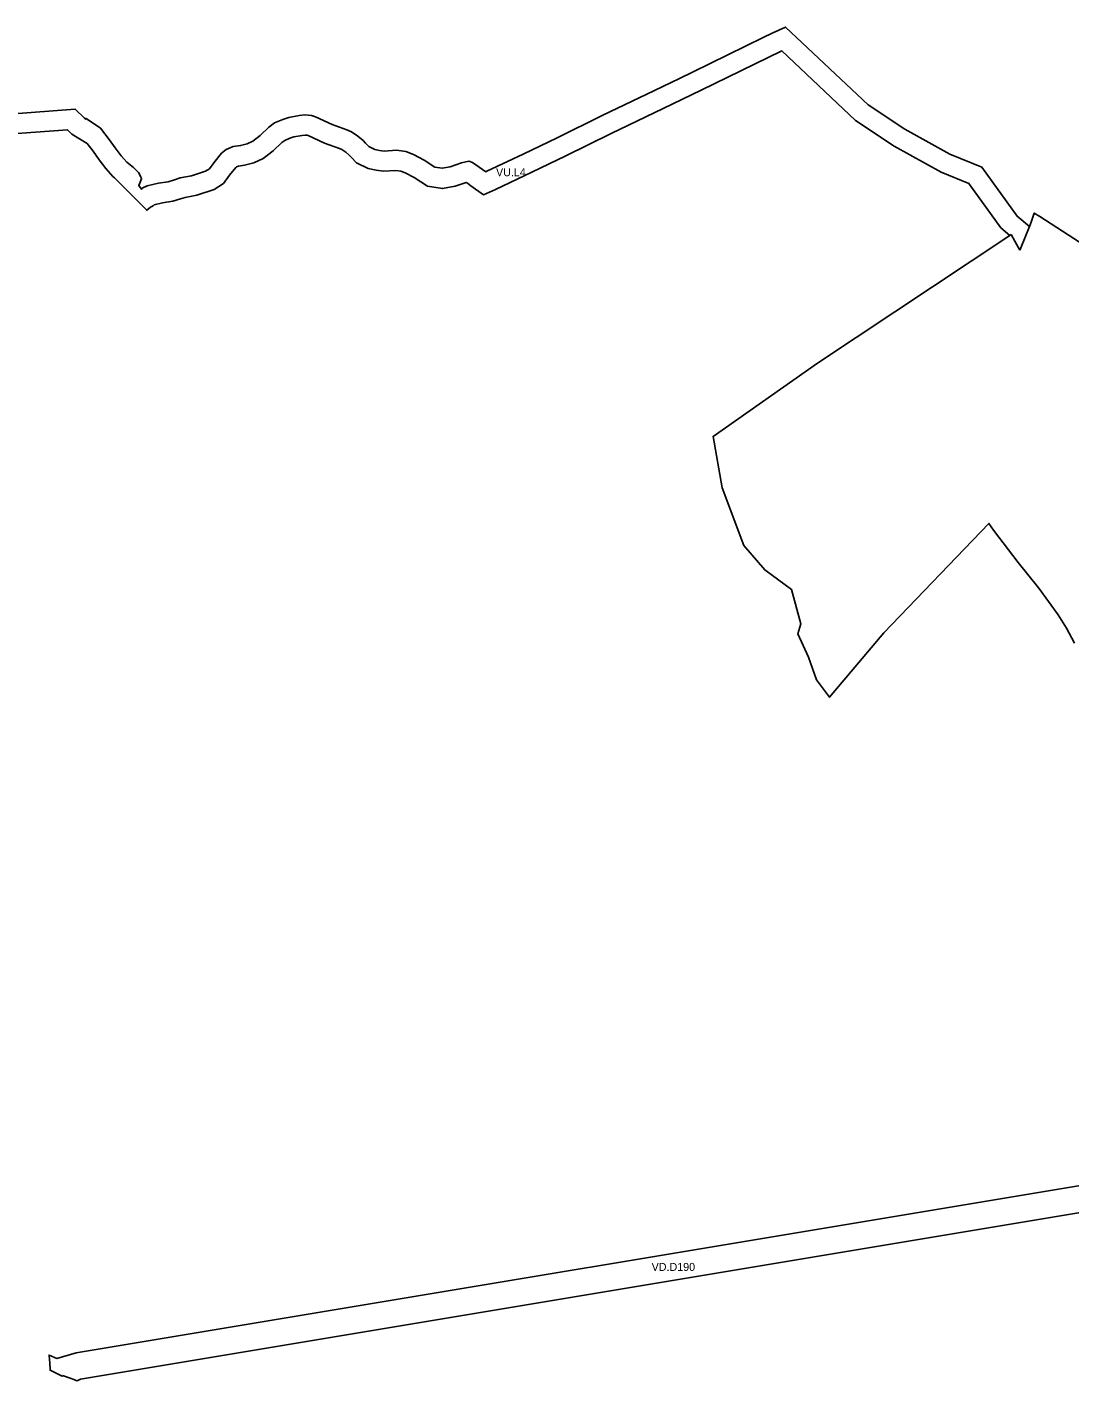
# Model space of a CAD drawing. Extents: x -439083 to -433688, y -1130252 to -1121189.
# Drawn here: x -437411 to -435848, y -1123219 to -1121189 of the extents above; entities that cross this region are included whole.
import ezdxf

# ---------------------------------------------------------------- set-up
doc = ezdxf.new("R2010")
doc.units = 0
for name, color, linetype in [('Vrstva 10', 7, 'Continuous'), ('Vrstva 13', 7, 'Continuous'), ('Vrstva 28', 7, 'Continuous'), ('Vrstva 31', 7, 'Continuous')]:
    doc.layers.add(name, color=color, linetype=linetype)

msp = doc.modelspace()

# ---------------------------------------------------------------- linework, layer by layer
at = {"layer": 'Vrstva 10'}
for p, q in [((-435791.5, -1122919.4), (-437337.2, -1123177)), ((-437330.6, -1123216.5), (-435767.3, -1122955.9)), ((-437357.5, -1123210.9), (-437344.7, -1123215.7))]:
    msp.add_line(p, q, dxfattribs=at)
for points in [[(-437337.2, -1123177), (-437365.9, -1123185.4), (-437377.6, -1123180.5), (-437376.9, -1123187.4), (-437376.9, -1123187.5), (-437376.7, -1123191.5), (-437376, -1123203.1), (-437374.1, -1123203.9), (-437361.9, -1123210), (-437357.9, -1123212), (-437357.5, -1123210.9)], [(-437344.7, -1123215.7), (-437342.2, -1123216.6), (-437335.4, -1123219.1), (-437330.6, -1123216.5)]]:
    msp.add_lwpolyline(points, dxfattribs=at)
at = {"layer": 'Vrstva 28'}
for p, q in [((-435937.7, -1121501.7), (-435935.6, -1121500.3)), ((-435935.6, -1121500.3), (-435937.7, -1121501.7)), ((-435935.6, -1121500.3), (-435932.6, -1121505.9)), ((-435932.6, -1121505.9), (-435935.6, -1121500.3)), ((-435921.2, -1121520.2), (-435908.2, -1121488.6)), ((-435908.2, -1121488.6), (-435921.2, -1121520.2)), ((-435932.6, -1121505.9), (-435922.8, -1121524)), ((-435922.8, -1121524), (-435932.6, -1121505.9)), ((-435922.8, -1121524), (-435921.2, -1121520.2)), ((-435921.2, -1121520.2), (-435922.8, -1121524))]:
    msp.add_line(p, q, dxfattribs=at)
for points in [[(-435908.2, -1121488.6), (-435926.8, -1121473), (-435979.5, -1121399.6), (-436027.7, -1121379.8), (-436095.2, -1121342.5), (-436150.2, -1121305.8), (-436273.7, -1121189.5), (-436293.6, -1121198.8), (-436307.3, -1121205.3), (-436413.3, -1121256.9), (-436432.8, -1121266.4), (-436470.3, -1121284.6), (-436548.5, -1121321.8), (-436616.1, -1121355.7), (-436667.1, -1121379.9), (-436721.3, -1121405.6), (-436722.9, -1121406.4), (-436733.1, -1121399.3), (-436743, -1121392.4), (-436748.4, -1121390.7), (-436759.7, -1121393.2), (-436776.5, -1121399), (-436788.2, -1121401.2), (-436799.2, -1121399.4), (-436815.3, -1121389.1), (-436831.3, -1121380.7), (-436842.9, -1121376.2), (-436856.7, -1121374.2), (-436875.3, -1121375.3), (-436882.6, -1121374.4), (-436889.5, -1121373.1), (-436898.6, -1121368.3), (-436903.3, -1121363.6), (-436906.9, -1121359.6), (-436914.9, -1121353.1), (-436924.1, -1121346.7), (-436931.4, -1121343.5), (-436953.5, -1121335.7), (-436978.2, -1121324.2), (-436984.5, -1121322.1), (-436994.2, -1121321.1), (-437003, -1121322.2), (-437018.2, -1121325), (-437027.3, -1121327.9), (-437039.6, -1121333.1), (-437048.4, -1121339.7), (-437061.1, -1121352.2), (-437072.4, -1121360.7), (-437080.8, -1121364.7), (-437090.6, -1121367.1), (-437101.9, -1121368.7), (-437112, -1121372.9), (-437119.2, -1121378.6), (-437130.8, -1121393.2), (-437137.1, -1121401.8), (-437143, -1121405.5), (-437163.9, -1121412.4), (-437181.2, -1121415.6), (-437189.8, -1121418.4), (-437199, -1121421.4), (-437213.5, -1121423.7), (-437230.6, -1121427.7), (-437237.9, -1121431.2), (-437239.1, -1121432.6), (-437243.2, -1121426.8), (-437239, -1121417.1), (-437240.5, -1121412.8), (-437243.7, -1121407.7), (-437251.2, -1121400.2), (-437261, -1121392), (-437269.4, -1121382.3), (-437278.5, -1121370.5), (-437287.6, -1121357.8), (-437300.4, -1121341.1), (-437322.2, -1121326.5), (-437322.7, -1121327.3), (-437324.6, -1121326.1), (-437338.5, -1121312.5), (-437477.2, -1121322.8)], [(-437466.8, -1121352.1), (-437349.8, -1121343.4), (-437343.3, -1121349.8), (-437320.7, -1121363.9), (-437311.7, -1121375.7), (-437302.6, -1121388.4), (-437292.6, -1121401.3), (-437282.1, -1121413.4), (-437279.7, -1121415.5), (-437231.3, -1121464.1), (-437225.8, -1121459.6), (-437221.5, -1121457.7), (-437219.9, -1121456), (-437207.7, -1121453.1), (-437192, -1121450.6), (-437180.6, -1121446.9), (-437173.8, -1121444.8), (-437156.4, -1121441.5), (-437130, -1121432.8), (-437116.4, -1121424.1), (-437107, -1121411.5), (-437097.9, -1121399.9), (-437096.7, -1121399), (-437093.9, -1121397.9), (-437084.8, -1121396.6), (-437070.7, -1121393.1), (-437056.7, -1121386.5), (-437041.5, -1121374.9), (-437028.8, -1121362.5), (-437024.5, -1121359.3), (-437016.9, -1121356.1), (-437010.8, -1121354.1), (-436998.4, -1121351.8), (-436993.9, -1121351.3), (-436990.8, -1121351.6), (-436989.2, -1121352.1), (-436964.9, -1121363.6), (-436942.4, -1121371.4), (-436938.8, -1121373), (-436933, -1121377), (-436927.7, -1121381.4), (-436925, -1121384.4), (-436916.6, -1121392.8), (-436899.5, -1121401.6), (-436887.2, -1121404.1), (-436876.2, -1121405.4), (-436857.9, -1121404.3), (-436850.6, -1121405.4), (-436843.8, -1121408), (-436830.4, -1121415), (-436810.2, -1121427.9), (-436787.9, -1121431.7), (-436768.8, -1121428.1), (-436752.4, -1121422.4), (-436750.6, -1121423.7), (-436745.5, -1121427.4), (-436726.6, -1121441.2), (-436708.5, -1121432.8), (-436654.2, -1121407), (-436602.9, -1121382.6), (-436535.3, -1121348.8), (-436457.3, -1121311.7), (-436400.2, -1121283.9), (-436280.5, -1121225.8), (-436279.4, -1121225.3), (-436169, -1121329.3), (-436110.8, -1121368.1), (-436040.7, -1121406.9), (-435998.9, -1121424.1), (-435951.1, -1121490.5), (-435937.7, -1121501.7)], [(-435824.6, -1121517.5), (-435892.7, -1121473.7), (-435901.1, -1121468.3), (-435905.5, -1121482), (-435908.2, -1121488.6)], [(-435937.7, -1121501.7), (-436226.1, -1121693.3), (-436382.5, -1121803.2), (-436369, -1121880.4), (-436336.2, -1121966.8), (-436304.9, -1122003.2), (-436264.9, -1122032.4), (-436250.7, -1122084.1), (-436255.2, -1122099), (-436239.5, -1122134.2), (-436227.5, -1122167.9), (-436208, -1122194.1), (-436126.4, -1122097.5), (-435969.1, -1121933.5), (-435962.1, -1121943.9), (-435924.9, -1121992.4), (-435894.3, -1122030.5), (-435865.1, -1122070.6), (-435852.8, -1122090.7), (-435840.6, -1122113.1)]]:
    msp.add_lwpolyline(points, dxfattribs=at)

# ---------------------------------------------------------------- texts
at = {"layer": 'Vrstva 13'}
msp.add_text('VD.D190', height=12, dxfattribs=at).set_placement((-436474.5, -1123054.2))
at = {"layer": 'Vrstva 31'}
msp.add_text('VU.L4', height=12, dxfattribs=at).set_placement((-436707.7, -1121413))

doc.saveas('drawing.dxf')
